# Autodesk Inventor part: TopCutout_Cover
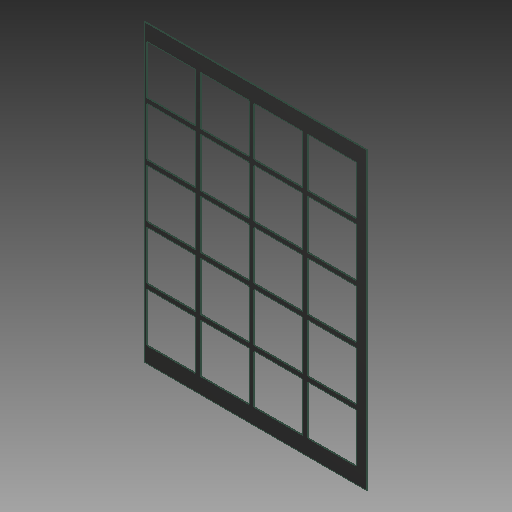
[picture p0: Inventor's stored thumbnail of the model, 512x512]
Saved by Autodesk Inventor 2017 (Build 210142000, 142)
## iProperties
Created: 2017-05
Part Number: TopCutout_Cover
Material: Generic
Document SubType Name: Modeling
Designer: Savy
Density: 1 g/cm^3
Appearance: Default
Mass: 109.385 g
Surface Area: 1607.74 cm^2
Volume: 109.385 cm^3
Author: Savy
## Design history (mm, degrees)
feature "SOLID1"
body "Solid1"
